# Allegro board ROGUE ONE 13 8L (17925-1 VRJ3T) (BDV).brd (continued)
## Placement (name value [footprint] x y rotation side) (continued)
PR4621  27K4R2F-GP  [R402H16]  54.14 77.87 180 bottom
PR4622  10R2F-L-GP  [R402H14]  48.15 78.81 180 bottom
PR4623  0R0402-PAD-1-GP  [0R0402-PAD]  48.93 78.67 180 bottom
PR4624  49D9R2F-GP  [R402H16]  49.7 78.86 180 bottom
PR4625  2K61R2F-1-GP  [R402H16]  40.17 72.79 180 bottom
PR4626  3K3R2F-2-GP  [R402H16]  53.73 75.88 90 bottom
PR4627  100R2F-L1-GP-U  [R402H14]  45.51 73.17 270 top
PR4628  9K31R2F-GP  [R402H16]  46.24 75.24 0 top
PR4629  100KR2F-L1-GP  [R402H16]  47 75.24 0 top
PR4630  2KR2F-3-GP  [R402H16]  53.73 75.11 90 bottom
PR4631  100R2F-L1-GP-U  [R402H14]  56.91 73.55 270 bottom
PR4632  301R2F-GP  [R402H16]  43.57 70.76 90 top
PR4633  2K55R2F-GP  [R402H16]  53.43 74.3 90 bottom
PR4635  1KR2F-3-GP  [R402H16]  53.89 66.06 180 bottom
PR4636  499R2F-2-GP  [R402H16]  53.43 73.54 90 bottom
PR4637  1K78R2F-GP  [R402H16]  43.09 71.77 90 bottom
PR4638  2KR2F-L1-GP  [R402H16]  42.84 69.97 90 top
PR4639  100R2F-L1-GP-U  [R402H14]  54.01 72.28 0 bottom
PR4640  2K49R2F-GP  [R402H16]  43.85 71.01 90 bottom
PR4641  2K61R2F-1-GP  [R402H16]  53.99 70.78 0 top
PR4642  536R2F-1-GP  [R402H16]  53.38 69.49 90 top
PR4643  11KR2F-L-GP  [R402H16]  52.87 70.63 180 bottom
PR4644  41K2R2F-GP  [R402H16]  45.89 71.27 90 top
PR4645  1KR2F-3-GP  [R402H16]  52.11 67.46 0 top
PR4646  NTC-10K-29-GP-U  [NTC-402H22-U]  71.16 92.45 270 bottom
PR4647  0R0402-PAD-1-GP  [0R0402-PAD]  53.38 69.23 270 bottom
PR4648  357R2F-GP  [R402H16]  43.09 69.49 90 bottom
PR4649  0R0402-PAD-1-GP  [0R0402-PAD]  41.29 66.72 0 bottom
PR4650  NTC-10K-29-GP-U  [NTC-402H22-U]  71.21 63.52 270 bottom
PR4651  1KR2F-3-GP  [R402H16]  43.09 68.73 90 bottom
PR4652  11KR2F-L-GP  [R402H16]  42.53 66.41 90 bottom
PR4653  2K61R2F-1-GP  [R402H16]  44.01 63.9 90 bottom
PR4654  NTC-470K-17-GP  [NTC-402H22-U]  62.29 64.28 90 bottom
PR4655  23K2R2F-GP  [R402H16]  49.32 65.42 0 bottom
PR4656  2K87R2F-1-GP  [R402H16]  49.19 67.33 0 top
PR4657  2KR2F-3-GP  [R402H16]  48.55 67.2 180 bottom
PR4658  499R2F-2-GP  [R402H16]  47.79 67.2 180 bottom
PR4659  100R2F-L1-GP-U  [R402H14]  45.76 66.95 90 bottom
PR4660  1K91R2F-1-GP  [R402H16]  47.03 67.2 180 bottom
PR4661  84K5R2F-GP  [R402H16]  51.6 66.9 180 bottom
PR4662  11KR2F-L-GP  [R402H16]  49.34 67.2 180 bottom
PR4663  100R2F-L1-GP-U  [R402H14]  47.41 64.41 90 bottom
PR4665  0R0402-PAD-1-GP  [0R0402-PAD]  56.05 72.79 90 bottom
PR4666  0R0402-PAD-1-GP  [0R0402-PAD]  56.05 72.03 90 bottom
PR4667  0R0402-PAD-1-GP  [0R0402-PAD]  46.14 64.92 0 bottom
PR4668  0R0402-PAD-1-GP  [0R0402-PAD]  45.38 64.92 0 bottom
PR4669  0R2J-2-GP  [R402H16]  51.6 69.36 270 bottom
PR4701  0R0402-PAD-1-GP  [0R0402-PAD]  40.53 66.72 0 bottom
PR4702  0R0402-PAD-1-GP  [0R0402-PAD]  59.48 65.3 90 bottom
PR4703  2D2R6J-3-GP  [R1206H28]  68.21 67.54 270 top
PR4704  2D2R2F-GP  [R402H16]  59.48 67.58 90 bottom
PR4705  2D2R3-1-U-GP  [R603H22]  59.2 68.6 270 bottom
PR4706  0R0402-PAD-1-GP  [0R0402-PAD]  59.48 66.06 90 bottom
PR4708  3K65R2F-1-GP  [R402H16]  44.01 64.66 270 bottom
PR4712  5K11R2F-L1-GP  [R402H16]  60.62 64.28 270 bottom
PR4802  0R0402-PAD-1-GP  [0R0402-PAD]  57.18 86.43 90 bottom
PR4803  2D2R2F-GP  [R402H16]  59.09 88.54 90 bottom
PR4804  2D2R3-1-U-GP  [R603H22]  58.89 89.58 270 bottom
PR4805  2D2R6J-3-GP  [R1206H28]  68.37 88.54 270 top
PR4806  0R0402-PAD-1-GP  [0R0402-PAD]  57.18 87.19 90 bottom
PR4808  3K65R2F-1-GP  [R402H16]  56.43 70.38 270 bottom
PR4809  10R2F-L-GP  [R402H14]  55.92 67.2 90 bottom
PR4810  2D2R3-1-U-GP  [R603H22]  58.97 78.38 270 bottom
PR4811  0R0402-PAD-1-GP  [0R0402-PAD]  59.48 75.08 90 bottom
PR4812  0R0402-PAD-1-GP  [0R0402-PAD]  59.48 75.84 90 bottom
PR4813  2D2R2F-GP  [R402H16]  58.89 77.36 90 bottom
PR4814  2D2R6J-3-GP  [R1206H28]  68.24 77.74 270 top
PR4815  10R2F-L-GP  [R402H14]  55.92 67.96 90 bottom
PR4816  3K65R2F-1-GP  [R402H16]  56.43 71.14 270 bottom
PR4817  5K11R2F-L1-GP  [R402H16]  60.72 86.2 180 bottom
PR4818  5K11R2F-L1-GP  [R402H16]  62.09 74.36 270 bottom
PR4821  100KR2F-L1-GP  [R402H16]  56.43 69.61 270 bottom
PR4822  100KR2F-L1-GP  [R402H16]  55.92 66.44 90 bottom
PR4823  100KR2F-L1-GP  [R402H16]  57.19 66.31 0 bottom
PR4824  100KR2F-L1-GP  [R402H16]  55.92 68.73 90 bottom
PR5001  2D2R3-1-U-GP  [R603H22]  175.05 103.52 180 bottom
PR5003  3K65R2F-1-GP  [R402H16]  41.82 76.73 0 top
PR5004  0R0402-PAD-1-GP  [0R0402-PAD]  43.73 78.25 0 top
PR5101  10K2R2F-GP  [R402H16]  50.08 57.3 180 bottom
PR5102  6K49R2F-1-GP  [R402H16]  53.38 63.39 270 bottom
PR5103  510KR2F-GP  [R402H16]  50.61 60.42 270 bottom
PR5104  100KR2J-1-GP  [R402H16]  50.97 61.23 270 bottom
PR5107  6K2R2F-GP  [R402H16]  50.84 57.3 0 bottom
PR5108  10R2F-L-GP  [R402H14]  52.62 64.15 270 bottom
PR5110  2D2R5F-2-GP  [R805H24]  59.98 59.45 90 top
PR5111  0R0603-PAD-2-GP-U  [0R0603-PAD-1-U]  55.46 54.45 270 bottom
PR5112  0R2J-2-GP  [R402H16]  50.69 59.3 270 bottom
PR5113  0R0402-PAD-2-GP  [0R0402-PAD-1]  50.69 58.54 270 bottom
PR5114  1MR2J-1-GP  [R402H16]  48.81 60.47 0 bottom
PR5201  88K7R2F-GP  [R402H16]  170.09 70.43 180 bottom
PR5202  3K16R2F-GP  [R402H16]  172.89 69.92 180 bottom
PR5203  100KR2F-L1-GP  [R402H16]  176.57 68.9 270 bottom
PR5204  10KR2F-2-GP  [R402H16]  172.12 69.92 0 bottom
PR5208  100KR2J-1-GP  [R402H16]  176.57 71.95 270 bottom
PR5209  0R0402-PAD-2-GP  [0R0402-PAD-1]  176.57 71.19 90 bottom
PR5210  47KR2F-GP  [R402H16]  176.57 69.66 90 bottom
PR5401  47KR2J-2-GP  [R402H16]  167.43 2.81 180 top
PR5402  100KR2F-L1-GP  [R402H16]  171.82 3.09 270 top
PR5403  16K5R2F-2-GP  [R402H16]  169.46 10.31 90 bottom
PR5404  13K3R2F-L1-GP  [R402H16]  168.7 8.78 90 bottom
PR5406  0R0402-PAD-2-GP  [0R0402-PAD-1]  168.95 2.81 0 top
PR5408  0R0402-PAD-2-GP  [0R0402-PAD-1]  170.22 2.3 270 top
PR5409  47KR2J-2-GP  [R402H16]  110.4 27.2 90 bottom
PR5410  10KR2F-2-GP  [R402H16]  110.66 22.62 90 bottom
PR5417  0R0402-PAD-2-GP  [0R0402-PAD-1]  110.36 27.96 270 bottom
PR5419  29K4R2F-GP  [R402H16]  118.71 25.85 0 bottom
PR5420  13K7R2F-GP  [R402H16]  119.17 27.09 270 bottom
PT4701  SE330U2VDM-4-GP  [CT7343H83]  78.27 65.68 180 bottom
PT4801  SE330U2VDM-4-GP  [CT7343H83]  78.27 89.43 0 bottom
PT4803  SE330U2VDM-4-GP  [CT7343H83]  78.27 77.23 180 bottom
PT4805  ST100U20VDM-3-GP  [CT7343H119]  48.81 43.83 270 bottom
PT4806  ST100U20VDM-3-GP  [CT7343H119]  57.19 82.95 90 bottom
PT4807  ST100U20VDM-3-GP  [CT7343H119]  65.95 96.67 270 bottom
PU4301  AON7403-GP-U  [PPAK-8P-3232H36]  41.19 84.47 270 bottom
PU4302  AON7403-GP-U  [PPAK-8P-3232H36]  37.89 82.44 180 bottom
PU4401  ISL9538HRTZ-GP-U  [QFN32J4-G2D85H34]  27.98 46.88 270 top
PU4403  AON7380-GP  [PPAK-8P-3232H36]  41.01 54.4 0 top
PU4404  AON7380-GP  [PPAK-8P-3232H36]  37.76 53.66 270 top
PU4405  AON7380-GP  [PPAK-8P-3232H36]  43.09 45.1 270 top
PU4406  AON7380-GP  [PPAK-8P-3232H36]  38.52 45.23 270 top
PU4412  AON7401-GP  [PPAK-8P-3232H36]  99.86 11.32 0 bottom
PU4501  SY8286BRAC-GP  [QFN20Z3-G1D1H36]  91.23 20.59 180 bottom
PU4502  SY8288CRAC-GP  [QFN20Z3-G1D1H36]  53.13 18.43 0 bottom
PU4601  ISL95859CHRTZ-T-1-GP  [QFN40J5-G3D6-DIFF-H34]  48.17 72.92 90 bottom
PU4701  AOZ5038QI-05-GP  [QFN31G5-G4P-9H34]  64.3 67.58 270 bottom
PU4801  AOZ5038QI-05-GP  [QFN31G5-G4P-9H34]  64.17 88.54 270 bottom
PU4802  AOZ5038QI-05-GP  [QFN31G5-G4P-9H34]  64.17 78.12 270 bottom
PU5001  ISL95808HRZ-T-1-GP  [DFN8G2-G1710-U1H40]  172.38 101.49 90 bottom
PU5002  AON7408-GP  [PPAK-8P-3232H36]  165.27 102.98 90 bottom
PU5003  AON7408-GP  [PPAK-8P-3232H36]  164 99.14 270 bottom
PU5101  G5388K11U-GP  [QFN32J4-G3PH32]  55.54 59.07 270 bottom
PU5201  AOZ2262QI-10-GP-U  [QFN22G4-G2PH42]  172.12 73.73 0 bottom
PU5401  APL5934KAI-TRG-GP-U  [SOIC8-G3530H63]  170.13 4.97 0 bottom
PU5403  APL5934KAI-TRG-GP-U  [SOIC8-G3530H63]  114.94 25.55 270 bottom
Q401  2N7002KDW-1-GP  [SOT-363H44]  137.86 85.08 0 top
Q501  PJA138KA-GP  [SOT23DGS2D4H44]  74.84 59.81 270 bottom
Q502  2N7002K-2-GP  [SOT23DGS2D4H44]  71.29 59.84 0 bottom
Q1701  PJT138KA-GP  [SOT-363H44]  185.08 59.84 90 top
Q1702  2N7002KDW-1-GP  [SOT-363H44]  135.7 49.7 90 bottom
Q1802  2N7002K-2-GP  [SOT23DGS2D4H44]  138.57 26.19 90 bottom
Q2001  PJT138KA-GP  [SOT-363H44]  130.06 50.78 0 bottom
Q2408  2N7002K-2-GP  [SOT23DGS2D4H44]  21.12 35.32 180 bottom
Q2414  2N7002K-2-GP  [SOT23DGS2D4H44]  17.57 17.67 0 bottom
Q2416  2N7002KDW-1-GP  [SOT-363H44]  26.84 20.08 180 top
Q2417  2N7002KDW-1-GP  [SOT-363H44]  9.49 23.08 180 top
Q2505  2N7002K-2-GP  [SOT23DGS2D4H44]  193.33 37.53 0 bottom
Q2507  PJA3415-GP  [SOT23DGS2D4H44]  185.21 64.66 90 top
Q2510  2N7002K-2-GP  [SOT23DGS2D4H44]  187.04 68.67 90 top
Q2601  2N7002KDW-1-GP  [SOT-363H44]  37 33.8 0 top
Q2602  2N7002K-2-GP  [SOT23DGS2D4H44]  22.65 10.31 270 bottom
Q2603  MMBT3904-5-GP-U  [SOT23CBE2D4H46-U]  75.07 94.23 270 top
Q4001  2N7002K-2-GP  [SOT23DGS2D4H44]  12.23 18.31 0 bottom
Q4002  PJA3415-GP  [SOT23DGS2D4H44]  176.32 9.42 90 bottom
Q4301  PJA138KA-GP  [SOT23DGS2D4H44]  50.23 96.16 180 bottom
Q4302  MMBT3904-5-GP-U  [SOT23CBE2D4H46-U]  50.23 93.49 180 bottom
Q4304  LMUN5212T1G-GP  [SOT323CBE2D2H40]  45.63 86.63 180 top
Q4305  LTA024EUB-FS8-GP  [SC70-2D2-312H44]  45 83.58 180 top
Q4348  PJA3415-GP  [SOT23DGS2D4H44]  37.89 74.06 0 bottom
Q4349  2N7002KDW-1-GP  [SOT-363H44]  17.69 46.5 90 bottom
Q5705  2N7002KDW-1-GP  [SOT-363H44]  35.09 86.99 0 top
Q6101  PJA3415-GP  [SOT23DGS2D4H44]  170.14 67.53 270 bottom
Q6102  2N7002K-2-GP  [SOT23DGS2D4H44]  173.44 67.38 0 bottom
Q6401  RN2418-GP  [SOT23CBE2D6H62]  8.04 21.1 270 bottom
Q6402  RN2418-GP  [SOT23CBE2D6H62]  8.04 17.67 270 bottom
Q6403  PJA138KA-GP  [SOT23DGS2D4H44]  43.85 17.54 0 bottom
Q6404  PJT138KA-GP  [SOT-363H44]  29.76 17.65 90 top
Q6501  PJA3402-R1-00001-GP  [SOT23DGS2D4H44]  76.52 11.5 270 bottom
Q6502  PJA3415-GP  [SOT23DGS2D4H44]  81.4 12.31 0 bottom
Q6503  2N7002K-2-GP  [SOT23DGS2D4H44]  91.86 13.61 0 bottom
Q6504  2N7002KDW-1-GP  [SOT-363H44]  86.93 11.8 180 bottom
Q6505  RN2418-GP  [SOT23CBE2D6H62]  12.23 15 180 bottom
Q7401  PJA3415-GP  [SOT23DGS2D4H44]  22.9 59.45 180 bottom
Q7404  2N7002KDW-1-GP  [SOT-363H44]  14.14 49.55 270 bottom
Q7405  2N7002KDW-1-GP  [SOT-363H44]  16.3 52.34 180 bottom
Q7406  PJT138KA-GP  [SOT-363H44]  19.09 53.99 0 bottom
Q7407  PJT138KA-GP  [SOT-363H44]  18.02 59.17 180 bottom
Q9201  PJA3415-GP  [SOT23DGS2D4H44]  181.37 80.28 270 bottom
Q9202  2N7002K-2-GP  [SOT23DGS2D4H44]  131.1 26.31 90 bottom
R301  1KR2J-1-GP  [R402H16]  99.61 93.24 270 bottom
R302  499R2F-2-GP  [R402H16]  101.39 93.24 270 bottom
R303  100KR2J-1-GP  [R402H16]  135.12 60.14 90 bottom
R304  49D9R2F-GP  [R402H16]  127.47 71.19 0 top
R305  49D9R2F-GP  [R402H16]  129.86 72.43 90 top
R308  1KR2J-1-GP  [R402H16]  120.03 93.03 270 bottom
R310  51R2J-2-GP  [R402H16]  97.52 93.49 270 bottom
R317  51R2J-2-GP  [R402H16]  102.86 85.64 180 top
R401  24D9R2F-L-GP  [R402H16]  113.93 84.47 270 top
R402  10KR2J-3-GP  [R402H16]  151.24 86.54 270 bottom
R403  100KR2J-1-GP  [R402H16]  134.84 84.37 180 top
R404  0R2J-2-GP  [R402H16]  136.06 86.53 270 top
R405  10KR2J-3-GP  [R402H16]  134.84 86.07 0 top
R406  10KR2J-3-GP  [R402H16]  134.79 82.52 90 top
R407  100KR2J-1-GP  [R402H16]  8.23 27.08 270 bottom
R501  121R2F-GP  [R402H16]  126.89 72.76 180 top
R502  80D6R2F-L-GP  [R402H16]  126.12 72.64 180 top
R503  100R2F-L1-GP-U  [R402H14]  125.36 72.64 180 top
R504  0R0402-PAD-2-GP  [0R0402-PAD-1]  137.76 57.09 90 top
R505  470R2F-GP  [R402H16]  137.33 55.87 180 top
R506  10KR2F-2-GP  [R402H16]  73.09 58.54 270 bottom
R507  10KR2F-2-GP  [R402H16]  70.85 57.83 270 bottom
R601  49D9R2F-GP  [R402H16]  107.99 86.51 90 top
R709  0R0402-PAD-2-GP  [0R0402-PAD-1]  90.46 94.25 180 bottom
R719  100R2F-L1-GP-U  [R402H14]  113.93 86.1 0 top
R720  100R2F-L1-GP-U  [R402H14]  114.9 86.1 180 top
R723  54D9R2F-L1-GP  [R402H16]  91.86 93.41 180 bottom
R726  100R2F-L1-GP-U  [R402H14]  91.73 94.63 90 bottom
R727  56R2J-4-GP  [R402H16]  93 94.51 180 bottom
R728  220R2J-L2-GP  [R402H16]  93.77 94.51 0 bottom
R732  0R0402-PAD-2-GP  [0R0402-PAD-1]  94.53 94 180 bottom
R807  100R2F-L1-GP-U  [R402H14]  97.83 86.51 270 top
R808  100R2F-L1-GP-U  [R402H14]  96.05 86.51 90 top
R809  100R2F-L1-GP-U  [R402H14]  120.69 84.47 270 top
R810  100R2F-L1-GP-U  [R402H14]  122.09 83.2 270 top
R811  D0002R5J-2-GP  [R805H16]  108.7 80.71 270 top
R812  D0002R5J-2-GP  [R805H16]  105.83 80.71 270 top
R813  D0002R5J-2-GP  [R805H16]  108.7 78.91 270 top
R814  D0002R5J-2-GP  [R805H16]  111.65 83.33 270 top
R815  D0002R5J-2-GP  [R805H16]  105.83 78.91 270 top
R1103  0R0603-PAD-2-GP-U  [0R0603-PAD-1-U]  140.63 73.4 270 top
R1104  0R0603-PAD-2-GP-U  [0R0603-PAD-1-U]  155.11 74.44 270 top
R1201  240R2D-GP  [R402H16]  53.4 39.13 270 top
R1202  2D7R2F-1-GP  [R402H16]  97.83 32.91 90 top
R1203  24D9R2F-L-GP  [R402H16]  95.67 32.15 270 top
R1204  240R2D-GP  [R402H16]  62.9 39.13 270 top
R1205  240R2D-GP  [R402H16]  83.2 39.13 270 top
R1208  49D9R2F-GP  [R402H16]  55.28 31.64 90 top
R1211  36R2F-1-GP  [R402H16]  47.66 36.85 270 top
R1212  240R2F-1-GP  [R402H16]  53.85 40.36 180 top
R1213  240R2F-1-GP  [R402H16]  63.35 40.36 180 top
R1214  240R2F-1-GP  [R402H16]  83.65 40.36 180 top
R1215  240R2F-1-GP  [R402H16]  73.5 40.36 180 top
R1220  0R2J-2-GP  [R402H16]  96.31 36.09 180 bottom
R1221  0R2J-2-GP  [R402H16]  95.42 36.09 180 bottom
R1222  1K8R2F-GP  [R402H16]  95.8 33.42 0 top
R1223  1K8R2F-GP  [R402H16]  96.56 33.42 0 top
R1224  36R2F-1-GP  [R402H16]  51.09 34.44 270 top
R1225  33R2F-3-GP  [R402H16]  51.09 37.74 270 top
R1226  33R2F-3-GP  [R402H16]  51.09 38.5 270 top
R1234  240R2D-GP  [R402H16]  73.05 39.13 270 top
R1301  240R2D-GP  [R402H16]  104.81 38.75 180 bottom
R1302  2D7R2F-1-GP  [R402H16]  104.56 30.75 180 top
R1303  24D9R2F-L-GP  [R402H16]  102.58 30.8 270 top
R1304  240R2D-GP  [R402H16]  115.39 39.13 270 top
R1305  240R2D-GP  [R402H16]  125.54 39.11 270 top
R1306  240R2D-GP  [R402H16]  135.69 39.13 270 top
R1311  36R2F-1-GP  [R402H16]  152.25 37.61 270 bottom
R1312  36R2F-1-GP  [R402H16]  148.63 35.2 270 bottom
R1313  33R2F-3-GP  [R402H16]  148.55 38.99 270 bottom
R1314  33R2F-3-GP  [R402H16]  148.55 39.78 270 bottom
R1320  1K8R2F-GP  [R402H16]  106.08 30.75 0 top
R1321  1K8R2F-GP  [R402H16]  105.32 30.75 0 top
R1330  49D9R2F-GP  [R402H16]  138.42 32.02 0 top
R1331  240R2F-1-GP  [R402H16]  104.81 40.53 0 bottom
R1332  240R2F-1-GP  [R402H16]  116.49 40.36 180 top
R1333  240R2F-1-GP  [R402H16]  126.64 40.34 180 top
R1334  240R2F-1-GP  [R402H16]  136.79 40.36 180 top
R1339  0R2J-2-GP  [R402H16]  104.05 36.98 180 bottom
R1340  0R2J-2-GP  [R402H16]  104.81 36.98 180 bottom
R1501  20KR2J-L2-GP  [R402H16]  147.33 58.97 270 top
R1502  1KR2J-1-GP  [R402H16]  142.96 73.83 270 bottom
R1503  1KR2J-1-GP  [R402H16]  144.67 74.59 270 bottom
R1504  4K7R2J-2-GP  [R402H16]  147.77 79.85 180 bottom
R1505  20KR2J-L2-GP  [R402H16]  149.21 80.94 270 bottom
R1506  100KR2F-L1-GP  [R402H16]  135.4 61.44 0 bottom
R1507  1KR2J-1-GP  [R402H16]  136.18 61.44 180 bottom
R1508  100KR2F-L1-GP  [R402H16]  140.17 61.11 90 bottom
R1509  4K7R2J-L-GP  [R402H15]  140.17 61.89 90 bottom
R1510  100KR2F-L1-GP  [R402H16]  142.58 61.11 0 bottom
R1511  4K7R2J-L-GP  [R402H15]  142.05 62.35 90 bottom
R1512  4K7R2J-2-GP  [R402H16]  142.13 53.08 90 top
R1513  4K7R2J-L-GP  [R402H15]  148.63 69.18 90 bottom
R1514  4K7R2J-L-GP  [R402H15]  146.09 69.97 270 bottom
R1515  20KR2J-L2-GP  [R402H16]  162.35 53.99 270 top
R1516  4K7R2J-2-GP  [R402H16]  161.58 55.21 180 top
R1517  1KR2J-1-GP  [R402H16]  96.31 92.8 0 bottom
R1518  1KR2J-1-GP  [R402H16]  90.72 90.06 90 bottom
R1519  10KR2J-3-GP  [R402H16]  146.32 77.03 90 bottom
R1520  4K7R2J-L-GP  [R402H15]  152.34 72.51 0 bottom
R1521  4K7R2J-2-GP  [R402H16]  151.55 72.51 0 bottom
R1522  4K7R2J-2-GP  [R402H16]  150.61 75.35 180 bottom
R1523  20KR2J-L2-GP  [R402H16]  151.17 73.81 270 bottom
R1524  100KR2F-L1-GP  [R402H16]  140.37 57.68 270 top
R1525  20KR2J-L2-GP  [R402H16]  139.84 56.91 270 top
R1527  1KR2J-1-GP  [R402H16]  142.66 72.54 0 bottom
R1551  4K7R2J-2-GP  [R402H16]  144.72 79.16 180 bottom
R1552  20KR2J-L2-GP  [R402H16]  145.94 78.71 270 bottom
R1553  20KR2J-L2-GP  [R402H16]  133.52 58.13 0 top
R1554  20KR2J-L2-GP  [R402H16]  148.02 76.24 90 bottom
R1555  20KR2J-L2-GP  [R402H16]  136.03 58.31 180 top
R1601  0R2J-2-GP  [R402H16]  132.37 83.84 270 top
R1602  0R2J-2-GP  [R402H16]  131.41 87.06 270 top
R1603  113R2F-GP  [R402H16]  132.14 85.06 90 top
R1604  100R2F-L1-GP-U  [R402H14]  133.49 86.25 180 top
R1606  10KR2J-3-GP  [R402H16]  151.24 87.33 90 bottom
R1608  10KR2J-3-GP  [R402H16]  151.24 85.73 90 bottom
R1701  10KR2J-3-GP  [R402H16]  148.81 83.94 90 bottom
R1702  1KR2J-1-GP  [R402H16]  132.3 49.8 90 bottom
R1704  0R0402-PAD-2-GP  [0R0402-PAD-1]  133.85 49.73 0 bottom
R1706  0R0402-PAD-2-GP  [0R0402-PAD-1]  121.91 56.13 270 bottom
R1707  10KR2J-3-GP  [R402H16]  128.36 72.03 0 top
R1708  0R2J-2-GP  [R402H16]  129.91 53.46 180 bottom
R1713  0R0402-PAD-2-GP  [0R0402-PAD-1]  142.15 51.45 90 top
R1714  10KR2J-3-GP  [R402H16]  114.77 93.95 90 bottom
R1715  100KR2J-1-GP  [R402H16]  140.48 51.88 270 top
R1716  100KR2F-L1-GP  [R402H16]  54.27 79.57 0 bottom
R1717  10KR2J-3-GP  [R402H16]  154.88 86.99 180 top
R1718  100KR2F-L1-GP  [R402H16]  52.41 79.98 90 bottom
R1719  47KR2F-GP  [R402H16]  52.24 80.79 90 bottom
R1721  10KR2J-3-GP  [R402H16]  127.78 59.45 90 bottom
R1722  10KR2J-3-GP  [R402H16]  128.94 60.75 0 bottom
R1723  10KR2J-3-GP  [R402H16]  131.61 58.31 0 top
R1726  10KR2J-3-GP  [R402H16]  182.54 58.69 270 top
R1727  100KR2J-1-GP  [R402H16]  182.54 57.9 90 top
R1728  0R0402-PAD-2-GP  [0R0402-PAD-1]  183.6 56.25 270 top
R1730  330KR2J-L1-GP  [R402H16]  146.88 54.83 270 top
R1731  100KR2F-L1-GP  [R402H16]  139.31 58.74 270 top
R1737  100KR2J-1-GP  [R402H16]  140.17 50.31 90 bottom
R1738  10KR2J-3-GP  [R402H16]  130.7 53.46 0 bottom
R1803  60D4R2F-GP  [R402H16]  135.93 91.64 270 bottom
R1804  0R0402-PAD-2-GP  [0R0402-PAD-1]  152.87 86.05 90 top
R1805  33R2F-3-GP  [R402H16]  130.01 58.31 0 top
R1806  0R0402-PAD-2-GP  [0R0402-PAD-1]  149.9 81.73 270 bottom
R1815  10MR2J-L-GP  [R402H16]  126.61 56.28 90 top
R1816  10KR2J-3-GP  [R402H16]  136.56 26.18 0 bottom
R1818  8K2R2F-1-GP  [R402H16]  133.52 55.8 90 top
R1819  10KR2J-3-GP  [R402H16]  151.09 80.89 90 bottom
R1820  10KR2J-3-GP  [R402H16]  130.8 58.31 180 top
R1821  10KR2J-3-GP  [R402H16]  132.37 58.31 180 top
R1837  150KR2J-GP  [R402H16]  135.24 58.11 180 top
R1839  0R0402-PAD-2-GP  [0R0402-PAD-1]  138.11 91.76 0 bottom
R1840  0R0402-PAD-2-GP  [0R0402-PAD-1]  137.35 91.76 0 bottom
R1841  1MR2J-1-GP  [R402H16]  137.81 93.01 90 bottom
R1901  200R2F-L-GP  [R402H16]  137.48 69.79 180 top
R1908  0R0402-PAD-2-GP  [0R0402-PAD-1]  170.85 24.28 90 bottom
R1909  1KR2J-1-GP  [R402H16]  172.25 26.05 0 top
R1910  10KR2J-3-GP  [R402H16]  144.67 72.38 90 bottom
R1911  10KR2J-3-GP  [R402H16]  144.69 73.17 270 bottom
R1912  33R2F-3-GP  [R402H16]  150.86 57.04 180 top
R1913  33R2F-3-GP  [R402H16]  148.15 56.61 270 top
R1920  33R2F-3-GP  [R402H16]  169.33 23.51 90 bottom
R1921  33R2F-3-GP  [R402H16]  172.89 24.53 0 bottom
R2001  10KR2F-2-GP  [R402H16]  130.01 48.51 0 bottom
R2002  10KR2J-3-GP  [R402H16]  128.41 50.61 180 bottom
R2005  10KR2J-3-GP  [R402H16]  145.63 81.53 180 bottom
R2008  10KR2J-3-GP  [R402H16]  146.42 81.53 0 bottom
R2009  10KR2J-3-GP  [R402H16]  152.41 83.08 0 top
R2010  10KR2J-3-GP  [R402H16]  153.2 83.08 180 top
R2011  10KR2J-3-GP  [R402H16]  149.16 72.23 90 bottom
R2012  10KR2J-3-GP  [R402H16]  146.34 72.26 90 bottom
R2013  10KR2J-3-GP  [R402H16]  149.44 69.97 90 bottom
R2014  10KR2J-3-GP  [R402H16]  147.77 69.97 90 bottom
R2015  10KR2J-3-GP  [R402H16]  146.37 75.41 90 bottom
R2016  10KR2J-3-GP  [R402H16]  149.16 75.38 90 bottom
R2017  10KR2J-3-GP  [R402H16]  146.37 74.62 90 bottom
R2018  10KR2J-3-GP  [R402H16]  149.16 74.59 90 bottom
R2019  0R0402-PAD-2-GP  [0R0402-PAD-1]  131.36 72.59 0 top
R2022  10KR2J-3-GP  [R402H16]  146.37 73.83 90 bottom
R2025  0R0402-PAD-2-GP  [0R0402-PAD-1]  133.59 57.98 180 bottom
R2026  0R0402-PAD-2-GP  [0R0402-PAD-1]  134.38 57.98 180 bottom
R2027  0R0402-PAD-2-GP  [0R0402-PAD-1]  137.2 102.13 90 bottom
R2028  0R2J-2-GP  [R402H16]  132.91 52.22 270 bottom
R2029  10KR2J-3-GP  [R402H16]  149.16 73.81 90 bottom
R2030  10KR2J-3-GP  [R402H16]  147.49 71.37 90 bottom
R2031  10KR2J-3-GP  [R402H16]  149.16 71.37 90 bottom
R2032  10KR2J-3-GP  [R402H16]  146.37 73.02 90 bottom
R2033  10KR2J-3-GP  [R402H16]  149.16 73.02 90 bottom
R2034  10KR2J-3-GP  [R402H16]  145.45 76.17 270 bottom
R2035  10KR2J-3-GP  [R402H16]  144.64 77.03 270 bottom
R2037  10KR2J-3-GP  [R402H16]  144.67 75.35 270 bottom
R2038  10KR2J-3-GP  [R402H16]  143.4 75.79 180 bottom
R2041  10KR2J-3-GP  [R402H16]  140.4 80.56 90 top
R2043  10KR2J-3-GP  [R402H16]  134.33 58.13 180 top
R2044  10KR2J-3-GP  [R402H16]  141.92 81.78 180 top
R2045  10KR2J-3-GP  [R402H16]  145.2 83.46 90 bottom
R2046  10KR2J-3-GP  [R402H16]  142.94 77.03 90 bottom
R2048  51KR2J-1-GP  [R402H16]  144.39 82.39 90 bottom
R2049  51KR2J-1-GP  [R402H16]  144.39 81.37 90 bottom
R2050  10KR2J-3-GP  [R402H16]  127.62 50.61 0 bottom
R2051  10KR2J-3-GP  [R402H16]  132.27 50.61 90 bottom
R2052  10KR2J-3-GP  [R402H16]  132.91 51.43 90 bottom
R2053  10KR2J-3-GP  [R402H16]  136.03 56.51 180 top
R2101  150R2F-1-GP  [R402H16]  138.75 70.2 270 top
R2102  0R2J-2-GP  [R402H16]  159.58 83.91 90 bottom
R2107  10KR2J-3-GP  [R402H16]  140.83 74.9 0 top
R2108  200R2F-L-GP  [R402H16]  136.56 78.76 270 top
R2109  10KR2J-3-GP  [R402H16]  154.45 83.38 90 top
R2110  10KR2J-3-GP  [R402H16]  154.45 82.62 90 top
R2111  10KR2J-3-GP  [R402H16]  149.21 79.37 90 bottom
R2112  10KR2J-3-GP  [R402H16]  149.21 80.16 270 bottom
R2113  10KR2J-3-GP  [R402H16]  138.09 74.31 270 top
R2114  10KR2J-3-GP  [R402H16]  138.09 73.53 270 top
R2115  10KR2J-3-GP  [R402H16]  149.21 78.58 90 bottom
R2116  10KR2J-3-GP  [R402H16]  149.67 77.36 180 bottom
R2117  10KR2J-3-GP  [R402H16]  134.15 77.46 90 top
R2118  10KR2J-3-GP  [R402H16]  134.05 79.62 180 top
R2119  0R0402-PAD-2-GP  [0R0402-PAD-1]  143.12 71.27 270 bottom
R2202  0R0603-PAD-2-GP-U  [0R0603-PAD-1-U]  145.56 96.18 90 bottom
R2203  0R0603-PAD-2-GP-U  [0R0603-PAD-1-U]  153.2 78.28 270 top
R2204  0R0603-PAD-2-GP-U  [0R0603-PAD-1-U]  152.19 56.03 180 top
R2205  0R0603-PAD-2-GP-U  [0R0603-PAD-1-U]  130.09 94.38 90 bottom
R2402  0R0402-PAD-2-GP  [0R0402-PAD-1]  21.63 13.23 0 bottom
R2409  0R2J-2-GP  [R402H16]  20.23 16.15 90 bottom
R2410  0R2J-2-GP  [R402H16]  28.97 25.32 90 top
R2414  10KR2J-3-GP  [R402H16]  25.57 32.4 180 bottom
R2415  10KR2J-3-GP  [R402H16]  36.87 32.4 270 bottom
R2417  100KR2J-1-GP  [R402H16]  23.79 34.82 270 bottom
R2418  0R2J-2-GP  [R402H16]  23.28 36.09 0 bottom
R2421  330R2J-3-GP  [R402H16]  20.44 20.08 180 bottom
R2423  330R2J-3-GP  [R402H16]  20.26 21.48 270 bottom
R2424  20KR2F-L-GP  [R402H16]  33.92 32.66 0 bottom
R2425  0R0402-PAD-2-GP  [0R0402-PAD-1]  31.94 27.73 180 top
R2430  10KR2J-3-GP  [R402H16]  41.34 26.51 0 bottom
R2431  10KR2J-3-GP  [R402H16]  22.67 13.78 270 top
R2432  1KR2J-1-GP  [R402H16]  21.12 29.48 0 bottom
R2434  100KR2J-1-GP  [R402H16]  31.15 32.66 180 bottom
R2437  43R2J-GP  [R402H16]  24.42 12.74 90 bottom
R2440  0R0402-PAD-2-GP  [0R0402-PAD-1]  41.31 13.86 270 bottom
R2441  100KR2F-L1-GP  [R402H16]  20.13 18.03 90 bottom
R2442  27KR2F-L-GP  [R402H16]  21.38 18.56 0 bottom
R2443  37K4R2F-1-GP  [R402H16]  23.79 22.88 270 top
R2444  100KR2F-L1-GP  [R402H16]  23.79 21.99 270 top
R2445  0R0402-PAD-2-GP  [0R0402-PAD-1]  18.2 20.59 270 bottom
R2446  0R0603-PAD-2-GP-U  [0R0603-PAD-1-U]  45 23.89 90 bottom
R2447  0R0402-PAD-2-GP  [0R0402-PAD-1]  29.63 32.66 0 bottom
R2448  10KR2F-2-GP  [R402H16]  34.68 32.66 0 bottom
R2449  10KR2F-2-GP  [R402H16]  34.68 26.08 270 top
R2451  100KR2J-1-GP  [R402H16]  23.36 27.68 0 top
R2452  100KR2J-1-GP  [R402H16]  41.31 12.97 270 bottom
R2453  100KR2J-1-GP  [R402H16]  43.09 12.97 90 bottom
R2454  100KR2J-1-GP  [R402H16]  23.94 24.58 270 top
R2455  100KR2J-1-GP  [R402H16]  42.58 14.37 0 bottom
R2456  100KR2J-1-GP  [R402H16]  32.68 14.37 270 top
R2457  115KR2F-GP  [R402H16]  27.09 23.51 90 top
R2459  0R0402-PAD-2-GP  [0R0402-PAD-1]  30.39 32.66 0 bottom
R2461  0R2J-2-GP  [R402H16]  22.26 27.25 180 bottom
R2462  0R0402-PAD-2-GP  [0R0402-PAD-1]  33.69 20.21 270 top
R2463  1KR2J-1-GP  [R402H16]  25.95 25.42 270 top
R2465  10KR2F-2-GP  [R402H16]  44.74 25.42 180 bottom
R2467  0R0402-PAD-2-GP  [0R0402-PAD-1]  7.84 23.08 0 top
R2468  0R0402-PAD-2-GP  [0R0402-PAD-1]  11.16 23.72 180 top
R2472  0R2J-2-GP  [R402H16]  26.33 26.69 0 top
R2473  0R0402-PAD-2-GP  [0R0402-PAD-1]  26.33 28.47 180 top
R2479  0R2J-2-GP  [R402H16]  23.92 12.97 90 top
R2480  100KR2J-1-GP  [R402H16]  34.35 6.6 90 top
R2481  0R2J-2-GP  [R402H16]  34.86 13.73 180 top
R2482  0R0402-PAD-2-GP  [0R0402-PAD-1]  34.86 24.61 180 top
R2489  100KR2J-1-GP  [R402H16]  18.2 19.83 90 bottom
R2494  0R2J-2-GP  [R402H16]  25.57 21.99 270 top
R2495  0R2J-2-GP  [R402H16]  28.49 19.45 180 top
R2496  100KR2J-1-GP  [R402H16]  42.41 25.16 270 bottom
R2497  100KR2J-1-GP  [R402H16]  24.12 27.68 0 top
R2498  0R2J-2-GP  [R402H16]  24.3 20.08 270 top
R2499  100KR2J-1-GP  [R402H16]  18.84 23.39 90 top
R2503  15R2F-2-GP  [R402H16]  153.63 57.4 270 bottom
R2504  10MR2J-L-GP  [R402H16]  192.83 40.79 90 top
R2505  0R2J-2-GP  [R402H16]  184.85 41.39 180 bottom
R2506  33R2F-3-GP  [R402H16]  137.28 56.3 180 bottom
R2507  33R2F-3-GP  [R402H16]  140.48 58.59 180 bottom
R2508  33R2F-3-GP  [R402H16]  138.9 58.06 0 bottom
R2509  33R2F-3-GP  [R402H16]  136.97 61.44 0 bottom
R2510  1KR2J-1-GP  [R402H16]  192.83 41.67 90 top
R2511  4K7R2J-2-GP  [R402H16]  185.21 67.58 270 top
R2512  0R2J-2-GP  [R402H16]  185.21 66.82 270 top
R2513  0R2J-2-GP  [R402H16]  156.48 70 90 bottom
R2514  10KR2J-3-GP  [R402H16]  158.79 71.39 180 bottom
R2516  0R0603-PAD-2-GP-U  [0R0603-PAD-1-U]  155.54 74.52 270 bottom
R2517  47KR2F-GP  [R402H16]  184.85 39.72 180 bottom
R2518  100KR2J-1-GP  [R402H16]  184.32 61.99 270 top
R2519  4K7R2J-2-GP  [R402H16]  153.12 59.5 180 bottom
R2520  100KR2J-1-GP  [R402H16]  159.68 71.39 180 bottom
R2522  0R5J-5-GP  [R805H24]  158.38 75.3 0 bottom
R2567  1MR2J-1-GP  [R402H16]  187.62 63.7 90 top
R2601  0R2J-2-GP  [R402H16]  27.85 10.43 90 bottom
R2602  0R0402-PAD-2-GP  [0R0402-PAD-1]  26.46 10.81 0 bottom
R2603  7K5R2F-1-GP  [R402H16]  42.46 29.86 0 bottom
R2604  7K5R2F-1-GP  [R402H16]  29.63 10.43 90 bottom
R2607  10KR2J-3-GP  [R402H16]  27.85 11.32 90 bottom
R2608  27KR2F-L-GP  [R402H16]  25.69 23.26 0 top
R2609  10R2F-L-GP  [R402H14]  165.11 66.67 0 bottom
R2610  NTC-100K-8-GP  [NTC-603H38]  163.31 66.69 180 bottom
R2611  0R0402-PAD-2-GP  [0R0402-PAD-1]  32.7 27.73 180 top
R2612  0R0603-PAD-2-GP-U  [0R0603-PAD-1-U]  187.87 67.33 270 bottom
R2613  0R0402-PAD-2-GP  [0R0402-PAD-1]  185.21 70.12 0 bottom
R2614  0R0402-PAD-2-GP  [0R0402-PAD-1]  184.44 70.12 0 bottom
R2615  0R2J-2-GP  [R402H16]  25.57 10.81 0 bottom
R2616  0R2J-2-GP  [R402H16]  14.42 14.9 180 bottom
R2705  0R0603-PAD-2-GP-U  [0R0603-PAD-1-U]  178.09 12.34 0 top
R2707  0R0603-PAD-2-GP-U  [0R0603-PAD-1-U]  170.47 16.4 90 top
R2712  0R0603-PAD-2-GP-U  [0R0603-PAD-1-U]  172 14.37 90 top
R2721  0R0402-PAD-2-GP  [0R0402-PAD-1]  169.25 18.86 270 bottom
R2724  0R0603-PAD-2-GP-U  [0R0603-PAD-1-U]  175.93 27.45 0 top
R2728  0R2J-2-GP  [R402H16]  183.3 17.49 90 bottom
R2730  0R0402-PAD-2-GP  [0R0402-PAD-1]  170.85 25.04 270 bottom
R2738  0R0402-PAD-2-GP  [0R0402-PAD-1]  169.25 18.1 270 bottom
R2739  0R0805-PAD-2-GP-U  [0R0805-PAD-1-U]  179.74 12.08 0 top
R2741  200KR2F-L-GP  [R402H16]  171.49 14.88 0 bottom
R2742  100KR2J-1-GP  [R402H16]  172.25 13.99 0 bottom
R2743  10KR2J-3-GP  [R402H16]  170.47 16.15 90 bottom
R2744  100KR2J-1-GP  [R402H16]  173.01 13.99 180 bottom
R2745  2K2R2J-2-GP  [R402H16]  181.83 13.25 270 bottom
R2746  0R2J-2-GP  [R402H16]  169.74 21.94 270 bottom
R2747  100KR2J-1-GP  [R402H16]  178.6 13.99 0 bottom
R2748  0R3J-0-U-GP  [R603H22]  169.71 13.35 0 bottom
R2749  0R0603-PAD-2-GP-U  [0R0603-PAD-1-U]  167.5 12.62 0 bottom
R2750  0R3J-0-U-GP  [R603H22]  174.66 27.45 0 top
R2751  0R0603-PAD-2-GP-U  [0R0603-PAD-1-U]  173.39 27.45 0 top
R2754  0R0402-PAD-2-GP  [0R0402-PAD-1]  181.12 17.49 90 bottom
R2907  0R0402-PAD-2-GP  [0R0402-PAD-1]  181.67 21.86 90 bottom
R2908  0R0603-PAD-2-GP-U  [0R0603-PAD-1-U]  175.58 37.05 0 top
R2909  0R0402-PAD-2-GP  [0R0402-PAD-1]  181.75 22.62 90 bottom
R2910  0R0603-PAD-2-GP-U  [0R0603-PAD-1-U]  181.14 37.23 0 top
R2921  0R0402-PAD-2-GP  [0R0402-PAD-1]  178.98 37.36 180 top
R2922  0R0402-PAD-2-GP  [0R0402-PAD-1]  176.95 37.48 180 top
R2923  0R0402-PAD-2-GP  [0R0402-PAD-1]  177.97 36.72 0 top
R4002  0R0402-PAD-2-GP  [0R0402-PAD-1]  52.36 78.73 180 bottom
R4004  10KR2J-3-GP  [R402H16]  182.16 66.31 90 bottom
R4005  1KR2J-1-GP  [R402H16]  16.17 20.11 0 bottom
R4006  20KR2F-L-GP  [R402H16]  93.51 15.51 90 top
R4009  10KR2J-3-GP  [R402H16]  94.86 11.4 90 top
R4010  0R0402-PAD-2-GP  [0R0402-PAD-1]  72.05 19.32 180 top
R4011  0R0402-PAD-2-GP  [0R0402-PAD-1]  48.68 62.5 90 bottom
R4014  0R2J-2-GP  [R402H16]  94.86 12.16 90 top
R4018  0R2J-2-GP  [R402H16]  182.16 67.96 90 bottom
R4019  0R2J-2-GP  [R402H16]  177.33 60.85 270 top
R4024  0R0402-PAD-2-GP  [0R0402-PAD-1]  153.58 90.7 270 bottom
R4029  0R0402-PAD-2-GP  [0R0402-PAD-1]  20.23 16.15 270 top
R4030  0R0402-PAD-2-GP  [0R0402-PAD-1]  20.23 16.91 270 top
R4031  100KR2J-1-GP  [R402H16]  20.23 18.43 270 top
R4032  100KR2J-1-GP  [R402H16]  20.23 19.2 270 top
R4033  0R2J-2-GP  [R402H16]  20.23 17.67 270 top
R4034  10KR2J-3-GP  [R402H16]  173.24 6.47 180 bottom
R4035  20KR2J-L2-GP  [R402H16]  174 6.47 0 bottom
R4036  0R0603-PAD-2-GP-U  [0R0603-PAD-1-U]  148.78 94.07 90 bottom
R4039  0R0402-PAD-2-GP  [0R0402-PAD-1]  182.16 67.07 90 bottom
R4040  0R2J-2-GP  [R402H16]  181.9 72.15 90 bottom
R4041  20KR2J-L2-GP  [R402H16]  181.9 72.92 270 bottom
R4042  20KR2J-L2-GP  [R402H16]  182.41 71.01 180 top
R4043  0R0603-PAD-2-GP-U  [0R0603-PAD-1-U]  151.17 64.79 90 bottom
R4045  0R6J-L-GP  [R1206H26]  152.69 62.96 90 bottom
R4301  0R0402-PAD-2-GP  [0R0402-PAD-1]  117.13 13.86 180 top
R4302  15KR2F-GP  [R402H16]  52.13 99.97 270 bottom
R4303  10KR2J-3-GP  [R402H16]  52.39 94.38 0 bottom
R4304  2K2R2J-2-GP  [R402H16]  32.09 32.71 0 top
R4305  33R2J-2-GP  [R402H16]  31.33 32.71 0 top
R4306  33R2J-2-GP  [R402H16]  50.46 99.21 270 bottom
R4307  240KR3-GP  [R603H22]  44.49 83.84 180 bottom
R4308  47KR2F-GP  [R402H16]  47.28 83.2 270 bottom
R4309  100KR2J-1-GP  [R402H16]  50.46 99.97 270 bottom
R4311  100KR2F-L1-GP  [R402H16]  20.61 47.26 180 bottom
R4315  18K7R2F-GP  [R402H16]  19.85 47.26 180 bottom
R4316  20KR2J-L2-GP  [R402H16]  40.17 81.55 180 bottom
R4317  0R0603-PAD-2-GP-U  [0R0603-PAD-1-U]  46.9 96.41 270 bottom
R4318  100KR2J-1-GP  [R402H16]  36.62 79.27 90 bottom
R4327  100R2J-2-GP  [R402H14]  116.12 17.42 270 top
R4333  10KR2F-2-GP  [R402H16]  17.69 48.79 0 bottom
R4368  0R0402-PAD-2-GP  [0R0402-PAD-1]  36.11 77.23 180 bottom
R4369  100KR2F-L1-GP  [R402H16]  19.09 49.93 180 bottom
R4370  100KR2F-L1-GP  [R402H16]  37.89 76.35 90 bottom
R4376  470KR2F-GP  [R402H16]  21.2 39.08 90 bottom
R4377  84K5R2F-GP  [R402H16]  21.2 39.9 270 bottom
R4378  100KR2J-1-GP  [R402H16]  18.45 43.45 90 top
R4379  100KR2F-L1-GP  [R402H16]  15.28 46.5 90 bottom
R5127  0R0805-PAD-2-GP-U  [0R0805-PAD-1-U]  50.97 47.52 180 top
R5501  0R0402-PAD-2-GP  [0R0402-PAD-1]  108.12 99.71 180 top
R5502  0R2J-2-GP  [R402H16]  100.5 101.11 180 top
R5503  0R0402-PAD-2-GP  [0R0402-PAD-1]  87.03 99.97 180 top
R5504  100KR2J-1-GP  [R402H16]  160.06 84.73 270 bottom
R5505  10KR2J-3-GP  [R402H16]  139.87 92.17 270 bottom
R5506  100R2J-2-GP  [R402H14]  97.32 101.24 180 top
R5507  100KR2J-1-GP  [R402H16]  139.87 91.41 270 bottom
R5508  0R5J-5-GP  [R805H24]  139.21 100.65 0 top
R5509  0R0805-PAD-2-GP-U  [0R0805-PAD-1-U]  135.27 102.46 0 top
R5510  0R0402-PAD-2-GP  [0R0402-PAD-1]  107.23 99.71 180 top
R5511  0R0603-PAD-2-GP-U  [0R0603-PAD-1-U]  111.34 99.97 270 top
R5515  0R3J-0-U-GP  [R603H22]  123.74 101.62 0 top
R5517  4K7R2J-2-GP  [R402H16]  132.12 100.98 270 top
R5518  4K7R2J-2-GP  [R402H16]  128.82 100.48 90 top
R5521  0R0402-PAD-2-GP  [0R0402-PAD-1]  130.72 99.08 180 top
R5522  0R0402-PAD-2-GP  [0R0402-PAD-1]  129.96 99.08 180 top
R5523  0R0402-PAD-2-GP  [0R0402-PAD-1]  141.97 95.12 180 bottom
R5541  31K6R2F-GP  [R402H16]  143.35 99.84 270 bottom
R5542  10KR2F-2-GP  [R402H16]  145.07 99.84 270 bottom
R5543  100R2J-2-GP  [R402H14]  85.51 99.97 180 top
R5544  100R2J-2-GP  [R402H14]  98.34 101.24 180 top
R5545  100R2J-2-GP  [R402H14]  99.61 101.11 180 top
R5546  0R0805-PAD-2-GP-U  [0R0805-PAD-1-U]  101.82 101.21 180 top
R5733  100KR2J-1-GP  [R402H16]  27.45 92.75 270 top
R5734  4D3KR2F-GP  [R402H16]  24.27 80.41 0 top
R5735  4K7R2J-2-GP  [R402H16]  25.08 87.24 270 bottom
R5738  4K7R2J-2-GP  [R402H16]  16.3 81.93 90 top
R5739  4K7R2J-2-GP  [R402H16]  16.3 81.17 90 top
R5740  4K7R2J-2-GP  [R402H16]  24.65 92.35 180 top
R5741  10KR2J-3-GP  [R402H16]  23.86 92.35 180 top
R5742  4K7R2J-2-GP  [R402H16]  34.08 84.22 180 bottom
R5743  4K7R2J-2-GP  [R402H16]  34.08 86 0 bottom
R5744  10KR2J-3-GP  [R402H16]  32.91 81.83 90 top
R5745  10KR2J-3-GP  [R402H16]  32.91 82.87 270 top
R5746  10KR2J-3-GP  [R402H16]  34.89 84.02 90 top
R5747  10KR2J-3-GP  [R402H16]  33.39 86.68 0 top
R5748  1K5R2F-2-GP  [R402H16]  20.41 80.94 270 top
R5749  0R2J-L-GP  [R402H15]  37.53 86.02 0 top
R5750  1MR2J-L3-GP  [R402H16]  21.91 82.29 270 top
R5751  2K2R2J-2-GP  [R402H16]  22.14 92.35 0 top
R5754  4K7R2J-2-GP  [R402H16]  23.79 88.41 0 bottom
R5755  2K2R2J-2-GP  [R402H16]  22.9 92.35 0 top
R5756  4K7R2J-2-GP  [R402H16]  22.75 80.41 180 top
R5757  4K7R2J-2-GP  [R402H16]  23.51 80.41 180 top
R5760  1KR2F-3-GP  [R402H16]  25.44 92.35 0 top
R5761  0R2J-2-GP  [R402H16]  21.27 92.55 180 top
R5762  68R2F-GP  [R402H16]  26.71 77.28 90 top
R5763  68R2F-GP  [R402H16]  25.03 77.28 270 top
R5764  100KR2J-1-GP  [R402H16]  20.31 92.42 0 top
R5765  5D1R2F-GP  [R402H16]  17.95 83.56 270 top
R5766  5D1R2F-GP  [R402H16]  17.95 84.32 270 top
R5767  5D1R2F-GP  [R402H16]  17.95 85.24 270 top
R5768  5D1R2F-GP  [R402H16]  17.95 86 270 top
R5769  5D1R2F-GP  [R402H16]  17.95 86.91 270 top
R5770  5D1R2F-GP  [R402H16]  17.95 87.67 270 top
R5771  3R2J-1-GP  [R402H16]  17.95 88.59 270 top
R5772  3R2J-1-GP  [R402H16]  17.95 89.35 270 top
R5773  5K1R2F-2-GP  [R402H16]  25.62 78.4 180 bottom
R5774  10KR2F-2-GP  [R402H16]  25.49 75.79 180 bottom
R5780  0R0603-PAD-2-GP-U  [0R0603-PAD-1-U]  18.45 92.09 90 top
R5781  0R0603-PAD-2-GP-U  [0R0603-PAD-1-U]  22.29 76.98 0 top
R5782  0R0603-PAD-2-GP-U  [0R0603-PAD-1-U]  19.62 76.98 0 top
R5783  0R0603-PAD-2-GP-U  [0R0603-PAD-1-U]  23.56 76.98 0 top
R5784  0R0603-PAD-2-GP-U  [0R0603-PAD-1-U]  20.94 76.98 0 top
R5785  0R0603-PAD-2-GP-U  [0R0603-PAD-1-U]  24.6 79.34 180 bottom
R5801  0R0402-PAD-1-GP  [0R0402-PAD]  16.3 82.7 270 top
R6005  100KR2F-L1-GP  [R402H16]  165.52 20.47 180 top
R6104  0R0402-PAD-2-GP  [0R0402-PAD-1]  168.49 69.33 180 top
R6105  0R0402-PAD-2-GP  [0R0402-PAD-1]  167.73 69.33 180 top
R6106  10KR2J-3-GP  [R402H16]  167.3 50.18 270 top
R6107  0R2J-2-GP  [R402H16]  168.44 52.85 90 top
R6108  0R2J-2-GP  [R402H16]  167.3 48.02 90 top
R6109  10KR2J-3-GP  [R402H16]  167.3 48.91 270 top
R6110  0R2J-2-GP  [R402H16]  176.19 66.31 270 bottom
R6111  10KR2J-3-GP  [R402H16]  171.49 67.33 90 top
R6112  20KR2J-L2-GP  [R402H16]  171.49 68.09 270 top
R6113  0R3J-0-U-GP  [R603H22]  171.74 62.12 270 top
R6114  0R0805-PAD-2-GP-U  [0R0805-PAD-1-U]  170.35 64.92 0 top
R6117  33R2J-2-GP  [R402H16]  153.96 40.02 90 top
R6118  10KR2J-3-GP  [R402H16]  154.09 86.48 180 top
R6119  71K5R2F-1-GP  [R402H16]  150.08 56.13 0 top
R6120  71K5R2F-1-GP  [R402H16]  148.15 55.82 270 top
R6121  20KR2J-L2-GP  [R402H16]  159.17 60.85 180 top
R6122  20KR2J-L2-GP  [R402H16]  162.35 53.23 90 top
R6123  20KR2J-L2-GP  [R402H16]  162.35 52.47 90 top
R6301  0R0402-PAD-2-GP  [0R0402-PAD-1]  190.41 14.24 90 top
R6302  0R0603-PAD-2-GP-U  [0R0603-PAD-1-U]  191.43 6.88 90 top
R6303  10KR2J-3-GP  [R402H16]  190.41 15.89 270 top
R6304  10KR2J-3-GP  [R402H16]  190.41 15.13 90 top
R6305  100KR2F-L1-GP  [R402H16]  188.76 5.73 0 top
R6306  0R0603-PAD-2-GP-U  [0R0603-PAD-1-U]  191.43 8.15 90 top
R6307  0R0603-PAD-2-GP-U  [0R0603-PAD-1-U]  150.28 19.7 90 top
R6308  0R0603-PAD-2-GP-U  [0R0603-PAD-1-U]  150.28 20.97 90 top
R6310  0R0402-PAD-2-GP  [0R0402-PAD-1]  153.58 16.27 90 top
R6311  0R0402-PAD-2-GP  [0R0402-PAD-1]  153.58 10.94 90 top
R6312  10KR2J-3-GP  [R402H16]  152.31 10.18 180 top
R6313  10KR2J-3-GP  [R402H16]  151.04 10.69 270 top
R6314  0R2J-2-GP  [R402H16]  152.79 3.57 90 top
R6315  0R2J-2-GP  [R402H16]  152.79 2.81 90 top
R6316  0R0402-PAD-2-GP  [0R0402-PAD-1]  176.57 4.21 0 top
R6401  499R2F-2-GP  [R402H16]  19.85 101.11 90 top
R6402  680R2F-GP  [R402H16]  19.85 99.33 90 top
R6405  10KR2J-3-GP  [R402H16]  175.81 2.81 270 bottom
R6406  10KR2J-3-GP  [R402H16]  176.19 7.13 90 bottom
R6419  0R2J-2-GP  [R402H16]  30.39 23.64 90 top
R6420  0R2J-2-GP  [R402H16]  42.69 16.48 270 top
R6421  0R0402-PAD-2-GP  [0R0402-PAD-1]  10.07 18.43 0 bottom
R6422  0R0402-PAD-2-GP  [0R0402-PAD-1]  10.2 21.74 180 bottom
R6502  0R3J-0-U-GP  [R603H22]  81.45 10.94 0 top
R6503  100R3J-4-GP  [R603H22]  92.16 11.37 270 bottom
R6504  20KR2F-L-GP  [R402H16]  79.16 12.97 0 bottom
R6505  0R2J-2-GP  [R402H16]  88.81 12.08 0 bottom
R6506  0R2J-2-GP  [R402H16]  84.77 12.29 90 bottom
R6507  51KR2J-1-GP  [R402H16]  73.95 13.73 90 bottom
R6508  100KR2J-1-GP  [R402H16]  75.65 13.73 270 bottom
R6509  100KR2J-1-GP  [R402H16]  77.36 13.73 270 bottom
R6510  0R0402-PAD-2-GP  [0R0402-PAD-1]  86.91 14.75 180 bottom
R6511  10KR2J-3-GP  [R402H16]  84.21 7.56 90 top
R6512  0R0402-PAD-2-GP  [0R0402-PAD-1]  15.13 16.25 90 bottom
R6513  1KR2J-1-GP  [R402H16]  59.98 4.72 180 top
R6801  0R2J-2-GP  [R402H16]  43.09 21.81 270 top
R6802  0R2J-2-GP  [R402H16]  41.47 25.16 270 top
R6803  0R2J-2-GP  [R402H16]  41.47 25.93 270 top
R7009  0R0402-PAD-2-GP  [0R0402-PAD-1]  171.62 45.87 0 top
R7010  0R0402-PAD-2-GP  [0R0402-PAD-1]  171.11 44.09 90 top
R7012  0R0402-PAD-2-GP  [0R0402-PAD-1]  172.38 45.87 0 top
R7013  0R0402-PAD-2-GP  [0R0402-PAD-1]  171.11 42.69 90 top
R7101  100KR2J-1-GP  [R402H16]  18.02 73.22 90 top
R7102  100KR2J-1-GP  [R402H16]  19.7 73.22 270 top
R7114  0R0402-PAD-2-GP  [0R0402-PAD-1]  22.44 73.88 180 top
R7116  0R0402-PAD-2-GP  [0R0402-PAD-1]  21.68 73.88 180 top
R7118  10KR2J-3-GP  [R402H16]  15.79 71.65 90 top
R7119  220KR2F-L-GP  [R402H16]  10.96 72.1 0 top
R7120  220KR2F-L-GP  [R402H16]  10.96 70.43 180 top
R7121  4K7R2J-2-GP  [R402H16]  17.31 70.38 180 bottom
R7122  220KR2F-L-GP  [R402H16]  10.81 66.69 0 top
R7123  220KR2F-L-GP  [R402H16]  10.81 65.02 180 top
R7124  0R0402-PAD-2-GP  [0R0402-PAD-1]  23.03 62.45 270 top
R7140  1KR2J-1-GP  [R402H16]  16.02 67.86 270 bottom
R7141  1KR2J-1-GP  [R402H16]  17.79 68.22 270 bottom
R7142  1KR2J-1-GP  [R402H16]  16.02 67.07 270 bottom
R7143  1KR2J-1-GP  [R402H16]  17.82 66.95 270 bottom
R7144  1KR2J-1-GP  [R402H16]  18.33 63.37 0 top
R7145  1KR2J-1-GP  [R402H16]  23.31 66.39 90 bottom
R7146  1KR2J-1-GP  [R402H16]  21.63 66.44 90 bottom
R7147  1KR2J-1-GP  [R402H16]  15.33 63.34 180 top
R7149  0R0402-PAD-2-GP  [0R0402-PAD-1]  20.92 73.88 180 top
R7151  0R0402-PAD-2-GP  [0R0402-PAD-1]  16.42 72.54 90 bottom
R7152  1KR2J-1-GP  [R402H16]  17.57 63.37 180 top
R7153  0R0402-PAD-2-GP  [0R0402-PAD-1]  16.42 71.77 90 bottom
R7170  1KR2J-1-GP  [R402H16]  14.57 63.34 0 top
R7171  1KR2J-1-GP  [R402H16]  23.33 68.5 90 bottom
R7172  1KR2J-1-GP  [R402H16]  21.38 68.22 180 bottom
R7173  1KR2J-1-GP  [R402H16]  21.63 69.49 90 bottom
R7174  1KR2J-1-GP  [R402H16]  23.33 69.26 90 bottom
R7201  0R0402-PAD-2-GP  [0R0402-PAD-1]  18.1 34.56 270 top
R7202  100KR2J-1-GP  [R402H16]  12.26 32.12 180 bottom
R7204  0R2J-2-GP  [R402H16]  7.07 36.37 270 bottom
R7206  15KR2F-GP  [R402H16]  14.85 36.14 0 bottom
R7208  1MR2J-1-GP  [R402H16]  6.97 36.67 90 top
R7211  0R0402-PAD-2-GP  [0R0402-PAD-1]  9.36 40.68 0 top
R7212  0R0402-PAD-2-GP  [0R0402-PAD-1]  7.99 40.71 0 top
R7214  1MR2J-1-GP  [R402H16]  6.34 34.44 90 top
R7215  100KR2F-L1-GP  [R402H16]  11.6 27.32 180 bottom
R7216  0R0402-PAD-2-GP  [0R0402-PAD-1]  7.2 29.1 0 bottom
R7217  0R0402-PAD-2-GP  [0R0402-PAD-1]  8.04 29.1 0 bottom
R7218  0R2J-2-GP  [R402H16]  10.45 29.1 180 bottom
R7219  0R2J-2-GP  [R402H16]  9.67 29.1 180 bottom
R7220  0R0402-PAD-2-GP  [0R0402-PAD-1]  15.79 40.05 0 top
R7221  0R0402-PAD-2-GP  [0R0402-PAD-1]  16.55 40.05 0 top
R7222  10KR2J-3-GP  [R402H16]  11.75 35.2 0 bottom
R7223  43KR2F-GP  [R402H16]  12.38 37.61 0 bottom
R7224  10KR2J-3-GP  [R402H16]  18.25 30.98 270 top
R7225  3K3R2J-3-GP  [R402H16]  11.09 24.91 90 bottom
R7226  3K3R2J-3-GP  [R402H16]  17.95 21.61 90 bottom
R7227  0R0402-PAD-2-GP  [0R0402-PAD-1]  8.85 29.1 0 bottom
R7228  3K3R2J-3-GP  [R402H16]  12.87 21.61 90 bottom
R7229  0R0402-PAD-2-GP  [0R0402-PAD-1]  6.41 35.2 270 top
R7230  3K3R2J-3-GP  [R402H16]  11.09 24.15 90 bottom
R7231  1MR2J-1-GP  [R402H16]  10.87 32.56 90 bottom
R7235  0R0402-PAD-2-GP  [0R0402-PAD-1]  11.22 29.1 0 bottom
R7236  0R0402-PAD-2-GP  [0R0402-PAD-1]  7.07 35.48 90 bottom
R7237  1MR2J-1-GP  [R402H16]  12.56 42.56 0 top
R7241  1MR2J-1-GP  [R402H16]  14.24 42.56 0 top
R7242  1MR2J-1-GP  [R402H16]  13.42 42.56 0 top
R7243  10KR2J-L-GP  [R402H15]  19.98 30.37 180 bottom
R7245  1MR2J-1-GP  [R402H16]  16.24 33.65 180 bottom
R7247  10KR2J-L-GP  [R402H15]  18.58 31.64 90 bottom
R7250  1MR2J-1-GP  [R402H16]  7.15 34.69 270 bottom
R7330  2MR2F-GP  [R402H16]  13.17 70.91 180 bottom
R7331  2MR2F-GP  [R402H16]  11.6 71.9 0 bottom
R7402  200KR2F-L-GP  [R402H16]  19.88 57.35 0 bottom
R7403  0R0402-PAD-2-GP  [0R0402-PAD-1]  20.21 60.09 270 bottom
R7404  1MR2F-GP  [R402H16]  20.21 58.57 270 bottom
R7405  100KR2F-L1-GP  [R402H16]  22.26 56.66 90 bottom
R7406  100KR2F-L1-GP  [R402H16]  22.26 57.42 270 bottom
R7407  1MR2F-GP  [R402H16]  22.47 56.46 0 top
R7408  200KR2F-L-GP  [R402H16]  14.19 51.63 90 bottom
R7409  200KR2F-L-GP  [R402H16]  12.31 50.59 0 bottom
R7410  200KR2F-L-GP  [R402H16]  17.16 54.78 0 bottom
R7411  1MR2F-GP  [R402H16]  12.84 58.03 270 top
R7422  1MR2F-GP  [R402H16]  15.91 59.71 90 bottom
R7423  100KR2F-L1-GP  [R402H16]  11.55 50.59 180 bottom
R7424  100KR2F-L1-GP  [R402H16]  16.8 61.49 0 top
R7425  100KR2F-L1-GP  [R402H16]  14.19 52.39 270 bottom
R7426  100KR2F-L1-GP  [R402H16]  14.29 54.48 270 bottom
R7427  100KR2F-L1-GP  [R402H16]  16.37 58.44 0 bottom
R7428  100KR2F-L1-GP  [R402H16]  18.15 57.22 270 bottom
R9126  0R3J-0-U-GP  [R603H22]  176.57 45.36 90 top
R9127  0R3J-0-U-GP  [R603H22]  178.98 45.36 270 top
R9130  0R2J-2-GP  [R402H16]  177.51 48.94 270 top
R9132  33R2J-2-GP  [R402H16]  138.11 57.19 0 bottom
R9133  33R2J-2-GP  [R402H16]  137.76 60.93 180 bottom
R9136  0R2J-2-GP  [R402H16]  177.2 54.76 90 top
R9137  0R2J-2-GP  [R402H16]  177.2 53.23 90 top
R9138  33R2J-2-GP  [R402H16]  138.82 60.93 180 bottom
R9139  0R2J-2-GP  [R402H16]  177.2 53.99 90 top
R9140  10KR2J-3-GP  [R402H16]  177.64 51.25 0 top
R9141  0R2J-2-GP  [R402H16]  181.04 45.13 270 top
R9143  0R3J-0-U-GP  [R603H22]  187.49 45.74 90 top
R9148  10KR2J-3-GP  [R402H16]  176.8 50.41 0 top
R9149  10KR2J-3-GP  [R402H16]  177.2 52.47 270 top
R9209  0R0402-PAD-2-GP  [0R0402-PAD-1]  175.93 89.05 270 bottom
R9210  0R0402-PAD-2-GP  [0R0402-PAD-1]  175.93 88.28 270 bottom
R9211  0R3J-0-U-GP  [R603H22]  186.17 90.06 270 bottom
R9212  100KR2J-1-GP  [R402H16]  133.14 25.93 0 bottom
R9213  0R0603-PAD-2-GP-U  [0R0603-PAD-1-U]  180.28 77.34 0 bottom
R9214  0R2J-2-GP  [R402H16]  181.78 86.89 0 bottom
R9215  100KR2J-1-GP  [R402H16]  181.01 86.89 180 bottom
R9216  0R0402-PAD-2-GP  [0R0402-PAD-1]  180.51 73.3 180 bottom
R9217  0R2J-2-GP  [R402H16]  182.03 82.44 270 bottom
R9218  0R0402-PAD-2-GP  [0R0402-PAD-1]  189.14 90.06 270 bottom
R9804  4K7R2F-GP  [R402H16]  189.98 27.25 0 top
R9805  1KR2F-3-GP  [R402H16]  190.29 28.97 0 top
R9806  0R0402-PAD-2-GP  [0R0402-PAD-1]  190.29 31.39 180 top
RAM1  MT40A256M16GE-083E-B-COLAY1-GP  [BGA96D0914H48-COLAY-4]  88.75 37.3 180 bottom
RAM2  MT40A256M16GE-083E-B-COLAY1-GP  [BGA96D0914H48-COLAY-4]  78.6 37.3 180 bottom
RAM3  MT40A256M16GE-083E-B-COLAY1-GP  [BGA96D0914H48-COLAY-4]  68.45 37.3 180 bottom
RAM4  MT40A256M16GE-083E-B-COLAY1-GP  [BGA96D0914H48-COLAY-4]  58.3 37.3 180 bottom
RAM5  MT40A256M16GE-083E-B-COLAY1-GP  [BGA96D0914H48-COLAY-4]  120.95 37.3 180 bottom
RAM6  MT40A256M16GE-083E-B-COLAY1-GP  [BGA96D0914H48-COLAY-4]  110.8 37.3 180 bottom
RAM7  MT40A256M16GE-083E-B-COLAY1-GP  [BGA96D0914H48-COLAY-4]  141.25 37.3 180 bottom
RAM8  MT40A256M16GE-083E-B-COLAY1-GP  [BGA96D0914H48-COLAY-4]  131.1 37.3 180 bottom
RN401  SRN2K2J-1-GP  [ARES2H16]  130.6 83.46 270 top
RN403  SRN2K2J-1-GP  [ARES2H16]  134.79 92.98 0 bottom
RN1202  SRN36J-GP  [ARES8-CN24-UH20]  51.09 36.09 90 top
RN1203  SRN36J-GP  [ARES8-CN24-UH20]  47.66 30.37 90 top
RN1204  SRN36J-GP  [ARES8-CN24-UH20]  51.09 30.37 90 top
RN1205  SRN36J-GP  [ARES8-CN24-UH20]  51.09 32.78 90 top
RN1206  SRN36J-GP  [ARES8-CN24-UH20]  47.66 32.78 90 top
RN1207  SRN36J-GP  [ARES8-CN24-UH20]  47.66 35.2 90 top
RN1302  SRN36J-GP  [ARES8-CN24-UH20]  148.63 37.1 90 bottom
RN1303  SRN36J-GP  [ARES8-CN24-UH20]  152.25 33.55 90 bottom
RN1304  SRN36J-GP  [ARES8-CN24-UH20]  148.69 31.13 90 bottom
RN1305  SRN36J-GP  [ARES8-CN24-UH20]  152.25 35.96 90 bottom
RN1306  SRN36J-GP  [ARES8-CN24-UH20]  148.69 33.55 90 bottom
RN1307  SRN36J-GP  [ARES8-CN24-UH20]  152.25 31.13 90 bottom
RN1601  SRN10KJ-6-GP  [ARES8-CN24-MUH20]  140.22 83.89 90 top
RN1703  SRN10KJ-L-GP  [SMD-ARES4H16]  123.81 57.02 180 bottom
RN1704  SRN10KJ-L-GP  [SMD-ARES4H16]  127.8 61.23 180 bottom
RN1801  SRN20KJ-1-GP  [SMD-ARES4H20]  141.26 49.09 270 bottom
RN1806  SRN15J-GP  [ARES8-CN24-MUH20]  123.1 53.23 270 bottom
RN1807  SRN2K2J-4-GP  [ARES8-CN24-UH20]  138.47 80.66 90 top
RN1811  SRN2K2J-1-GP  [ARES2H16]  143.17 79.14 270 bottom
RN1813  SRN10KJ-6-GP  [ARES8-CN24-MUH20]  144.34 55.11 90 top
RN2007  SRN1KJ-7-GP  [SMD-ARES4H18]  140.65 76.65 180 top
RN2008  SRN1KJ-7-GP  [SMD-ARES4H18]  138.09 75.46 270 top
RN2402  SRN4K7J-8-GP  [SMD-ARES4H18]  28.49 32.66 0 bottom
RN2403  SRN10KJ-6-GP  [ARES8-CN24-MUH20]  41.77 4.69 0 top
RN2404  SRN10KJ-6-GP  [ARES8-CN24-MUH20]  39.23 4.69 0 top
RN2405  SRN100KJ-5-GP  [ARES8-CN24H20]  30.9 20.21 270 top
RN2409  SRN100KJ-5-GP  [ARES8-CN24H20]  46.27 4.72 0 top
RN2410  SRN100KJ-5-GP  [ARES8-CN24H20]  55.16 4.72 0 top
RN2411  SRN100KJ-5-GP  [ARES8-CN24H20]  51.45 4.72 0 top
RN2412  SRN100KJ-5-GP  [ARES8-CN24H20]  48.81 4.72 0 top
RN2413  SRN2K2J-1-GP  [ARES2H16]  12.74 21.48 180 top
RN2602  SRN2K2J-1-GP  [ARES2H16]  38.85 32.35 90 bottom
RN2702  SRN1KJ-7-GP  [SMD-ARES4H18]  179.62 9.64 90 bottom
RN2703  SRN2K2J-1-GP  [ARES2H16]  168.85 20.01 270 bottom
RN2901  SRN2K2J-1-GP  [ARES2H16]  181.6 20.72 90 bottom
RN4302  SRN100J-3-GP  [SMD-ARES4H18]  114.34 18.81 180 top
RN5502  SRN100KJ-5-GP  [ARES8-CN24H20]  98.08 99.33 0 top
RN5503  SRN33J-5-GP-U  [SMD-ARES4H18]  173.01 96.06 270 top
RN5504  SRN33J-5-GP-U  [SMD-ARES4H18]  170.73 96.06 90 top
RN6501  SRN10KJ-L-GP  [SMD-ARES4H16]  89.19 11.83 180 top
RN6502  SRN33J-5-GP-U  [SMD-ARES4H18]  89.19 9.26 180 top
RN6503  SRN2K2J-1-GP  [ARES2H16]  83.76 8.98 0 top
RN7202  SRN10KJ-L-GP  [SMD-ARES4H16]  14.47 33.62 90 bottom
RN7206  SRN2K2J-1-GP  [ARES2H16]  18.3 32.15 90 top
RN7207  SRN100KJ-5-GP  [ARES8-CN24H20]  17.95 37.48 270 bottom
RTC1  ETY-CON2-22-GP-U  [3703K-Q02N-11L-U]  188.6 37.8 180 bottom
SPK1  ACES-CON6-20-GP-U  [50224-0060N-W01]  14.2 8.3 180 bottom
SPR1  SPRING-31-GP-U  [SPR6035H166]  77.7 56.3 180 bottom
SPR2  SPRING-31-GP-U  [SPR6035H166]  83 26.8 180 bottom
SSD1  SKT-NGFF75P-146-GP  [NFSM0-S6701-TP20]  192.5 13.4 270 bottom
SSD2  SKT-NGFF75P-146-GP  [NFSM0-S6701-TP20]  160.7 12.9 90 bottom
TCBD1  ACES-CON20-29-GP-U  [51530-02001-W01-U]  126.7 99.3 0 bottom
TP302  TPAD14-OP-GP  [TPAD14-OP]  99.86 92.22 180 bottom
TP303  TPAD14-OP-GP  [TPAD14-OP]  99 91.13 180 bottom
TP304  TPAD14-OP-GP  [TPAD14-OP]  133.87 81.25 0 top
TP305  TPAD14-OP-GP  [TPAD14-OP]  102.4 92.22 180 bottom
TP306  TPAD14-OP-GP  [TPAD14-OP]  103.32 90.98 180 bottom
TP307  TPAD14-OP-GP  [TPAD14-OP]  100.55 91.15 180 bottom
TP308  TPAD14-OP-GP  [TPAD14-OP]  98.57 92.27 180 bottom
TP309  TPAD14-OP-GP  [TPAD14-OP]  101.84 85.24 0 top
TP310  TPAD14-OP-GP  [TPAD14-OP]  95.04 91.59 180 bottom
TP311  TPAD14-OP-GP  [TPAD14-OP]  97.78 91.33 180 bottom
TP312  TPAD14-OP-GP  [TPAD14-OP]  92.16 91.61 180 bottom
TP313  TPAD14-OP-GP  [TPAD14-OP]  106.16 85.31 0 top
TP314  TPAD14-OP-GP  [TPAD14-OP]  104.94 85.34 0 top
TP315  TPAD14-OP-GP  [TPAD14-OP]  94.25 92.52 180 bottom
TP316  TPAD14-OP-GP  [TPAD14-OP]  97.35 92.5 180 bottom
TP317  TPAD14-OP-GP  [TPAD14-OP]  93.38 91.59 180 bottom
TP402  TPAD14-OP-GP  [TPAD14-OP]  141.99 93.64 180 bottom
TP618  TPAD14-OP-GP  [TPAD14-OP]  101.16 92.22 180 bottom
TP619  TPAD14-OP-GP  [TPAD14-OP]  91.05 87.93 180 bottom
TP620  TPAD14-OP-GP  [TPAD14-OP]  140.27 69.94 0 top
TP621  TPAD14-OP-GP  [TPAD14-OP]  96.23 91.33 180 bottom
TP1201  TPAD14-OP-GP  [TPAD14-OP]  53.51 32.15 0 top
TP1202  TPAD14-OP-GP  [TPAD14-OP]  84.04 32.43 0 top
TP1203  TPAD14-OP-GP  [TPAD14-OP]  63.74 32.43 0 top
TP1204  TPAD14-OP-GP  [TPAD14-OP]  73.89 32.43 0 top
TP1301  TPAD14-OP-GP  [TPAD14-OP]  105.7 32.91 0 top
TP1302  TPAD14-OP-GP  [TPAD14-OP]  127.02 32.4 0 top
TP1303  TPAD14-OP-GP  [TPAD14-OP]  116.88 32.43 0 top
TP1304  TPAD14-OP-GP  [TPAD14-OP]  137.17 32.43 0 top
TP1603  TPAD14-OP-GP  [TPAD14-OP]  142.41 86.48 90 bottom
TP1705  TPAD14-OP-GP  [TPAD14-OP]  115.84 92.83 0 bottom
TP1706  TPAD14-OP-GP  [TPAD14-OP]  128.87 63.16 180 bottom
TP1707  TPAD14-OP-GP  [TPAD14-OP]  153.81 26.08 180 bottom
TP1708  TPAD14-OP-GP  [TPAD14-OP]  134.33 62.68 180 bottom
TP1709  TPAD14-OP-GP  [TPAD14-OP]  174.94 55.06 0 top
TP1710  TPAD14-OP-GP  [TPAD14-OP]  126.73 69.89 0 top
TP1711  TPAD14-OP-GP  [TPAD14-OP]  183.76 70.6 0 top
TP1712  TPAD14-OP-GP  [TPAD14-OP]  147.41 84.02 180 bottom
TP1713  TPAD14-OP-GP  [TPAD14-OP]  126.02 58.51 180 bottom
TP1714  TPAD14-OP-GP  [TPAD14-OP]  127.17 57.55 180 bottom
